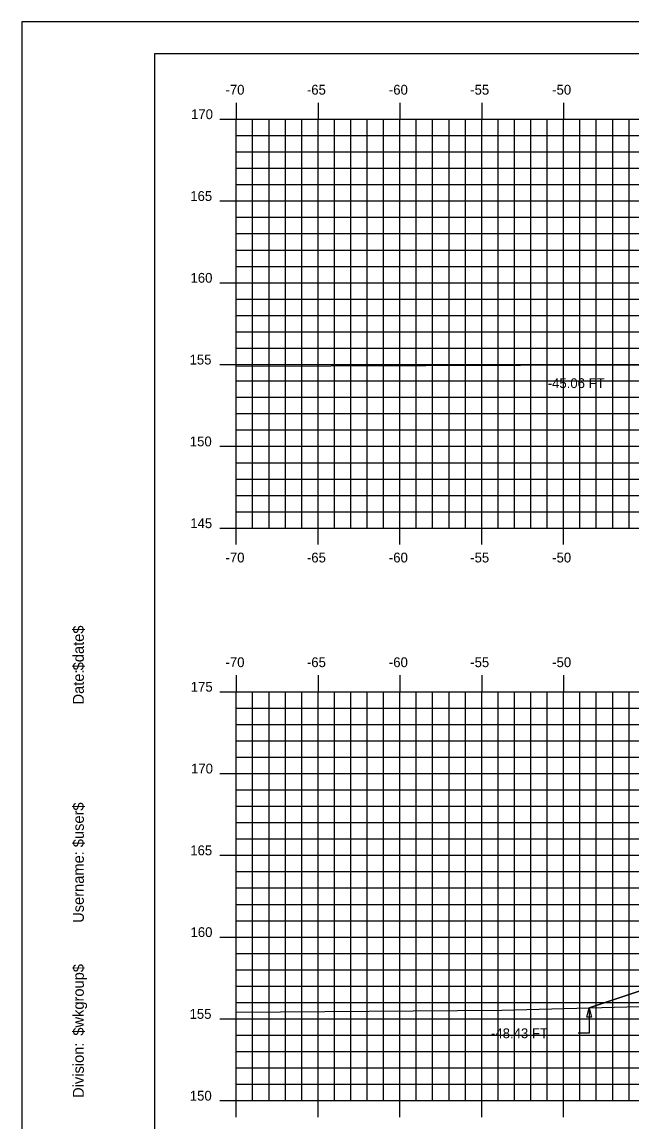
# Model space of a CAD drawing. Extents: x 1140981 to 1141151, y 608981 to 609091.
# Drawn here: x 1140980.7 to 1141017.9, y 609024.1 to 609091.3 of the extents above; entities that cross this region are included whole.
import ezdxf

# ---------------------------------------------------------------- set-up
doc = ezdxf.new("R2010")
doc.units = 0
for name, color, linetype in [('BORDER', 7, 'Continuous'), ('D_Roadway_SlopeLines', 7, 'Continuous'), ('D_Text_Standard', 7, 'Continuous'), ('H_V ANNOTATION', 7, 'Continuous'), ('MAJOR', 7, 'Continuous'), ('MINOR', 7, 'Continuous'), ('PLOT BOUNDARY', 7, 'Continuous'), ('S_Roadway_Centerline', 7, 'Continuous')]:
    doc.layers.add(name, color=color, linetype=linetype)

msp = doc.modelspace()

# ---------------------------------------------------------------- linework, layer by layer
msp.add_lwpolyline([(1141015.324, 609031.014), (1141031.055, 609036.258), (1141034.055, 609037.258), (1141041.302, 609039.673), (1141041.303, 609039.673), (1141052.758, 609040.132), (1141063.758, 609040.352), (1141074.758, 609040.132), (1141081.758, 609039.852), (1141089.29, 609037.341), (1141092.29, 609036.341), (1141104.882, 609032.144)])
at = {"layer": 'BORDER'}
msp.add_lwpolyline([(1140988.758, 608984.335), (1141148.758, 608984.335), (1141148.758, 609089.335), (1140988.758, 609089.335)], close=True, dxfattribs=at)
at = {"layer": 'D_Roadway_SlopeLines'}
msp.add_lwpolyline([(1141031.055, 609036.258), (1141015.324, 609031.014)], dxfattribs=at)
at = {"layer": 'D_Text_Standard'}
msp.add_lwpolyline([(1141015.324, 609031.014), (1141015.319, 609029.453), (1141014.639, 609029.453)], dxfattribs=at)
msp.add_lwpolyline([(1141015.324, 609031.014), (1141015.468, 609030.431), (1141015.177, 609030.432)], close=True, dxfattribs=at)
at = {"layer": 'MAJOR'}
for p, q in [((1140993.758, 609086.337), (1140993.758, 609085.335)), ((1140998.758, 609086.337), (1140998.758, 609085.335)), ((1141003.758, 609086.337), (1141003.758, 609085.335)), ((1141008.758, 609086.337), (1141008.758, 609085.335)), ((1141013.758, 609086.337), (1141013.758, 609085.335)), ((1140992.756, 609085.335), (1140993.758, 609085.335)), ((1140993.758, 609085.335), (1141133.758, 609085.335)), ((1140993.758, 609060.335), (1140993.758, 609085.335)), ((1140993.758, 609060.335), (1140993.758, 609085.335)), ((1140993.758, 609085.335), (1141133.758, 609085.335)), ((1140998.758, 609060.335), (1140998.758, 609085.335)), ((1141003.758, 609060.335), (1141003.758, 609085.335)), ((1141008.758, 609060.335), (1141008.758, 609085.335)), ((1141013.758, 609060.335), (1141013.758, 609085.335)), ((1140992.756, 609080.335), (1140993.758, 609080.335)), ((1140993.758, 609080.335), (1141133.758, 609080.335)), ((1140992.756, 609075.335), (1140993.758, 609075.335)), ((1140993.758, 609075.335), (1141133.758, 609075.335)), ((1140992.756, 609070.335), (1140993.758, 609070.335)), ((1140993.758, 609070.335), (1141133.758, 609070.335)), ((1140992.756, 609065.335), (1140993.758, 609065.335)), ((1140993.758, 609065.335), (1141133.758, 609065.335)), ((1140992.756, 609060.335), (1140993.758, 609060.335)), ((1140993.758, 609060.335), (1141133.758, 609060.335)), ((1140993.758, 609060.335), (1141133.758, 609060.335)), ((1140993.758, 609059.333), (1140993.758, 609060.335)), ((1140998.758, 609059.333), (1140998.758, 609060.335)), ((1141003.758, 609059.333), (1141003.758, 609060.335)), ((1141008.758, 609059.333), (1141008.758, 609060.335)), ((1141013.758, 609059.333), (1141013.758, 609060.335)), ((1140993.758, 609051.337), (1140993.758, 609050.335)), ((1140998.758, 609051.337), (1140998.758, 609050.335)), ((1141003.758, 609051.337), (1141003.758, 609050.335)), ((1141008.758, 609051.337), (1141008.758, 609050.335)), ((1141013.758, 609051.337), (1141013.758, 609050.335)), ((1140992.756, 609050.335), (1140993.758, 609050.335)), ((1140993.758, 609050.335), (1141133.758, 609050.335)), ((1140993.758, 609025.335), (1140993.758, 609050.335)), ((1140993.758, 609025.335), (1140993.758, 609050.335)), ((1140993.758, 609050.335), (1141133.758, 609050.335)), ((1140998.758, 609025.335), (1140998.758, 609050.335)), ((1141003.758, 609025.335), (1141003.758, 609050.335)), ((1141008.758, 609025.335), (1141008.758, 609050.335)), ((1141013.758, 609025.335), (1141013.758, 609050.335)), ((1140992.756, 609045.335), (1140993.758, 609045.335)), ((1140993.758, 609045.335), (1141133.758, 609045.335)), ((1140992.756, 609040.335), (1140993.758, 609040.335)), ((1140993.758, 609040.335), (1141133.758, 609040.335)), ((1140992.756, 609035.335), (1140993.758, 609035.335)), ((1140993.758, 609035.335), (1141133.758, 609035.335)), ((1140992.756, 609030.335), (1140993.758, 609030.335)), ((1140993.758, 609030.335), (1141133.758, 609030.335)), ((1140992.756, 609025.335), (1140993.758, 609025.335)), ((1140993.758, 609025.335), (1141133.758, 609025.335)), ((1140993.758, 609025.335), (1141133.758, 609025.335)), ((1140993.758, 609024.333), (1140993.758, 609025.335)), ((1140998.758, 609024.333), (1140998.758, 609025.335)), ((1141003.758, 609024.333), (1141003.758, 609025.335)), ((1141008.758, 609024.333), (1141008.758, 609025.335)), ((1141013.758, 609024.333), (1141013.758, 609025.335))]:
    msp.add_line(p, q, dxfattribs=at)
at = {"layer": 'MINOR'}
for p, q in [((1140994.758, 609060.335), (1140994.758, 609085.335)), ((1140995.758, 609060.335), (1140995.758, 609085.335)), ((1140996.758, 609060.335), (1140996.758, 609085.335)), ((1140997.758, 609060.335), (1140997.758, 609085.335)), ((1140999.758, 609060.335), (1140999.758, 609085.335)), ((1141000.758, 609060.335), (1141000.758, 609085.335)), ((1141001.758, 609060.335), (1141001.758, 609085.335)), ((1141002.758, 609060.335), (1141002.758, 609085.335)), ((1141004.758, 609060.335), (1141004.758, 609085.335)), ((1141005.758, 609060.335), (1141005.758, 609085.335)), ((1141006.758, 609060.335), (1141006.758, 609085.335)), ((1141007.758, 609060.335), (1141007.758, 609085.335)), ((1141009.758, 609060.335), (1141009.758, 609085.335)), ((1141010.758, 609060.335), (1141010.758, 609085.335)), ((1141011.758, 609060.335), (1141011.758, 609085.335)), ((1141012.758, 609060.335), (1141012.758, 609085.335)), ((1141014.758, 609060.335), (1141014.758, 609085.335)), ((1141015.758, 609060.335), (1141015.758, 609085.335)), ((1141016.758, 609060.335), (1141016.758, 609085.335)), ((1141017.758, 609060.335), (1141017.758, 609085.335)), ((1140993.758, 609084.335), (1141133.758, 609084.335)), ((1140993.758, 609084.335), (1140994.76, 609084.335)), ((1140993.758, 609083.335), (1141133.758, 609083.335)), ((1140993.758, 609083.335), (1140994.76, 609083.335)), ((1140993.758, 609082.335), (1141133.758, 609082.335)), ((1140993.758, 609082.335), (1140994.76, 609082.335)), ((1140993.758, 609081.335), (1141133.758, 609081.335)), ((1140993.758, 609081.335), (1140994.76, 609081.335)), ((1140993.758, 609079.335), (1141133.758, 609079.335)), ((1140993.758, 609079.335), (1140994.76, 609079.335)), ((1140993.758, 609078.335), (1141133.758, 609078.335)), ((1140993.758, 609078.335), (1140994.76, 609078.335)), ((1140993.758, 609077.335), (1141133.758, 609077.335)), ((1140993.758, 609077.335), (1140994.76, 609077.335)), ((1140993.758, 609076.335), (1141133.758, 609076.335)), ((1140993.758, 609076.335), (1140994.76, 609076.335)), ((1140993.758, 609074.335), (1141133.758, 609074.335)), ((1140993.758, 609074.335), (1140994.76, 609074.335)), ((1140993.758, 609073.335), (1141133.758, 609073.335)), ((1140993.758, 609073.335), (1140994.76, 609073.335)), ((1140993.758, 609072.335), (1141133.758, 609072.335)), ((1140993.758, 609072.335), (1140994.76, 609072.335)), ((1140993.758, 609071.335), (1141133.758, 609071.335)), ((1140993.758, 609071.335), (1140994.76, 609071.335)), ((1140993.758, 609069.335), (1141133.758, 609069.335)), ((1140993.758, 609069.335), (1140994.76, 609069.335)), ((1140993.758, 609068.335), (1141133.758, 609068.335)), ((1140993.758, 609068.335), (1140994.76, 609068.335)), ((1140993.758, 609067.335), (1141133.758, 609067.335)), ((1140993.758, 609067.335), (1140994.76, 609067.335)), ((1140993.758, 609066.335), (1141133.758, 609066.335)), ((1140993.758, 609066.335), (1140994.76, 609066.335)), ((1140993.758, 609064.335), (1141133.758, 609064.335)), ((1140993.758, 609064.335), (1140994.76, 609064.335)), ((1140993.758, 609063.335), (1141133.758, 609063.335)), ((1140993.758, 609063.335), (1140994.76, 609063.335)), ((1140993.758, 609062.335), (1141133.758, 609062.335)), ((1140993.758, 609062.335), (1140994.76, 609062.335)), ((1140993.758, 609061.335), (1141133.758, 609061.335)), ((1140993.758, 609061.335), (1140994.76, 609061.335)), ((1140994.758, 609025.335), (1140994.758, 609050.335)), ((1140995.758, 609025.335), (1140995.758, 609050.335)), ((1140996.758, 609025.335), (1140996.758, 609050.335)), ((1140997.758, 609025.335), (1140997.758, 609050.335)), ((1140999.758, 609025.335), (1140999.758, 609050.335)), ((1141000.758, 609025.335), (1141000.758, 609050.335)), ((1141001.758, 609025.335), (1141001.758, 609050.335)), ((1141002.758, 609025.335), (1141002.758, 609050.335)), ((1141004.758, 609025.335), (1141004.758, 609050.335)), ((1141005.758, 609025.335), (1141005.758, 609050.335)), ((1141006.758, 609025.335), (1141006.758, 609050.335)), ((1141007.758, 609025.335), (1141007.758, 609050.335)), ((1141009.758, 609025.335), (1141009.758, 609050.335)), ((1141010.758, 609025.335), (1141010.758, 609050.335)), ((1141011.758, 609025.335), (1141011.758, 609050.335)), ((1141012.758, 609025.335), (1141012.758, 609050.335)), ((1141014.758, 609025.335), (1141014.758, 609050.335)), ((1141015.758, 609025.335), (1141015.758, 609050.335)), ((1141016.758, 609025.335), (1141016.758, 609050.335)), ((1141017.758, 609025.335), (1141017.758, 609050.335)), ((1140993.758, 609049.335), (1141133.758, 609049.335)), ((1140993.758, 609049.335), (1140994.76, 609049.335)), ((1140993.758, 609048.335), (1141133.758, 609048.335)), ((1140993.758, 609048.335), (1140994.76, 609048.335)), ((1140993.758, 609047.335), (1141133.758, 609047.335)), ((1140993.758, 609047.335), (1140994.76, 609047.335)), ((1140993.758, 609046.335), (1141133.758, 609046.335)), ((1140993.758, 609046.335), (1140994.76, 609046.335)), ((1140993.758, 609044.335), (1141133.758, 609044.335)), ((1140993.758, 609044.335), (1140994.76, 609044.335)), ((1140993.758, 609043.335), (1141133.758, 609043.335)), ((1140993.758, 609043.335), (1140994.76, 609043.335)), ((1140993.758, 609042.335), (1141133.758, 609042.335)), ((1140993.758, 609042.335), (1140994.76, 609042.335)), ((1140993.758, 609041.335), (1141133.758, 609041.335)), ((1140993.758, 609041.335), (1140994.76, 609041.335)), ((1140993.758, 609039.335), (1141133.758, 609039.335)), ((1140993.758, 609039.335), (1140994.76, 609039.335)), ((1140993.758, 609038.335), (1141133.758, 609038.335)), ((1140993.758, 609038.335), (1140994.76, 609038.335)), ((1140993.758, 609037.335), (1141133.758, 609037.335)), ((1140993.758, 609037.335), (1140994.76, 609037.335)), ((1140993.758, 609036.335), (1141133.758, 609036.335)), ((1140993.758, 609036.335), (1140994.76, 609036.335)), ((1140993.758, 609034.335), (1141133.758, 609034.335)), ((1140993.758, 609034.335), (1140994.76, 609034.335)), ((1140993.758, 609033.335), (1141133.758, 609033.335)), ((1140993.758, 609033.335), (1140994.76, 609033.335)), ((1140993.758, 609032.335), (1141133.758, 609032.335)), ((1140993.758, 609032.335), (1140994.76, 609032.335)), ((1140993.758, 609031.335), (1141133.758, 609031.335)), ((1140993.758, 609031.335), (1140994.76, 609031.335)), ((1140993.758, 609029.335), (1141133.758, 609029.335)), ((1140993.758, 609029.335), (1140994.76, 609029.335)), ((1140993.758, 609028.335), (1141133.758, 609028.335)), ((1140993.758, 609028.335), (1140994.76, 609028.335)), ((1140993.758, 609027.335), (1141133.758, 609027.335)), ((1140993.758, 609027.335), (1140994.76, 609027.335)), ((1140993.758, 609026.335), (1141133.758, 609026.335)), ((1140993.758, 609026.335), (1140994.76, 609026.335))]:
    msp.add_line(p, q, dxfattribs=at)
at = {"layer": 'PLOT BOUNDARY'}
msp.add_lwpolyline([(1140980.664, 608981.276), (1141150.664, 608981.276), (1141150.664, 609091.276), (1140980.664, 609091.276)], close=True, dxfattribs=at)
at = {"layer": 'S_Roadway_Centerline'}
for points in [[(1140993.758, 609070.235), (1141016.927, 609070.323), (1141025.835, 609070.211), (1141031.23, 609070.816), (1141045.025, 609071.913), (1141046.887, 609072.758), (1141050.236, 609074.313), (1141052.144, 609074.689), (1141053.6, 609074.965), (1141057.959, 609075.178), (1141064.255, 609075.378), (1141069.594, 609075.216), (1141075.604, 609075.039), (1141077.446, 609074.821), (1141079.228, 609074.497), (1141085.647, 609072.383), (1141088.632, 609071.329), (1141093.986, 609070.537), (1141096.999, 609070.318), (1141110.65, 609070.157), (1141115.506, 609070.212)], [(1140993.758, 609030.733), (1141009.977, 609030.874), (1141026.763, 609031.313), (1141030.432, 609031.56), (1141045.208, 609032.752), (1141047.834, 609033.947), (1141049.661, 609034.555), (1141051.778, 609034.94), (1141052.932, 609035.025), (1141057.344, 609035.19), (1141063.779, 609035.507), (1141070.513, 609035.304), (1141074.764, 609035.173), (1141076.322, 609035.016), (1141078.692, 609034.736), (1141083.759, 609032.911), (1141084.999, 609032.561), (1141091.498, 609032.059), (1141093.213, 609032.024), (1141099.245, 609031.951), (1141112.53, 609032.405)]]:
    msp.add_lwpolyline(points, dxfattribs=at)

# ---------------------------------------------------------------- texts
at = {"layer": 'BORDER'}
for s, p in [('$date$', (1140984.443, 609051.64)), ('Date:', (1140984.443, 609049.552)), ('$user$', (1140984.443, 609040.827)), ('Username:', (1140984.443, 609036.203)), ('$wkgroup$', (1140984.443, 609029.305)), ('Division:', (1140984.443, 609025.501))]:
    msp.add_text(s, height=0.6696, rotation=90, dxfattribs=at).set_placement(p)
at = {"layer": 'D_Text_Standard'}
for s, p in [('-45.06 FT', (1141012.789, 609068.895)), ('-48.43 FT', (1141009.324, 609029.153))]:
    msp.add_text(s, height=0.6, dxfattribs=at).set_placement(p)
at = {"layer": 'H_V ANNOTATION'}
for s, p in [('-70', (1140993.099, 609086.835)), ('-65', (1140998.075, 609086.835)), ('-60', (1141003.083, 609086.835)), ('-55', (1141008.054, 609086.835)), ('-50', (1141013.062, 609086.835)), ('170', (1140990.994, 609085.335)), ('165', (1140990.946, 609080.335)), ('160', (1140990.962, 609075.335)), ('155', (1140990.903, 609070.335)), ('150', (1140990.919, 609065.335)), ('145', (1140990.946, 609060.335)), ('-70', (1140993.099, 609058.235)), ('-65', (1140998.075, 609058.235)), ('-60', (1141003.083, 609058.235)), ('-55', (1141008.054, 609058.235)), ('-50', (1141013.062, 609058.235)), ('-70', (1140993.099, 609051.835)), ('-65', (1140998.075, 609051.835)), ('-60', (1141003.083, 609051.835)), ('-55', (1141008.054, 609051.835)), ('-50', (1141013.062, 609051.835)), ('175', (1140990.978, 609050.335)), ('170', (1140990.994, 609045.335)), ('165', (1140990.946, 609040.335)), ('160', (1140990.962, 609035.335)), ('155', (1140990.903, 609030.335)), ('150', (1140990.919, 609025.335))]:
    msp.add_text(s, height=0.6, dxfattribs=at).set_placement(p)
at = {"layer": 'MAJOR'}
for p in [(1140993.753, 609060.335), (1140993.753, 609025.335)]:
    msp.add_text('-', height=0.006, dxfattribs=at).set_placement(p)

doc.saveas('drawing.dxf')
